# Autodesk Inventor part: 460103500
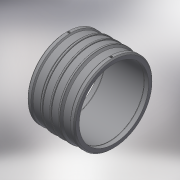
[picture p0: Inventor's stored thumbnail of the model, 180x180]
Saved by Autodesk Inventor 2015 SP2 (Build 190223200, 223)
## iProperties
Created: 2017-06
Part Number: 460103500
Material: Generic
Description: PLASSON LIGHTFIT COUPLER 500
Document SubType Name: Modeling
Designer: KIM
Mass: 17149.5 g
Surface Area: 12936.2 cm^2
Volume: 17149.5 cm^3
Density: 1 g/cm^3
Appearance: Default
Author: KIM
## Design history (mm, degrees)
derived "460103.ipt"
feature "Solid1::460103.ipt"
tag "TaggingFeature1"
body "Solid1"
other parameters: "d14" = 17.6296, "d19" = 3.52592, "d20" = 168 deg, "d22" = 566, "d23" = 576, "d24" = 549.02, "d25" = 135 deg, "d26" = 136, "d27" = 135 deg, "d29" = 283, "d35" = 15, "d39" = 0, "d40" = 4, "d41" = 14, "d42" = 0, "d43" = 135 deg, "d44" = 37.4, "d45" = 13.6, "d46" = 13.6, "d47" = 13.6, "d48" = 564.48, "d49" = 576, "d50" = 2.88, "d51" = 6, "d52" = 0, "D_" = 576, "A_" = 283, "d_2" = 12
